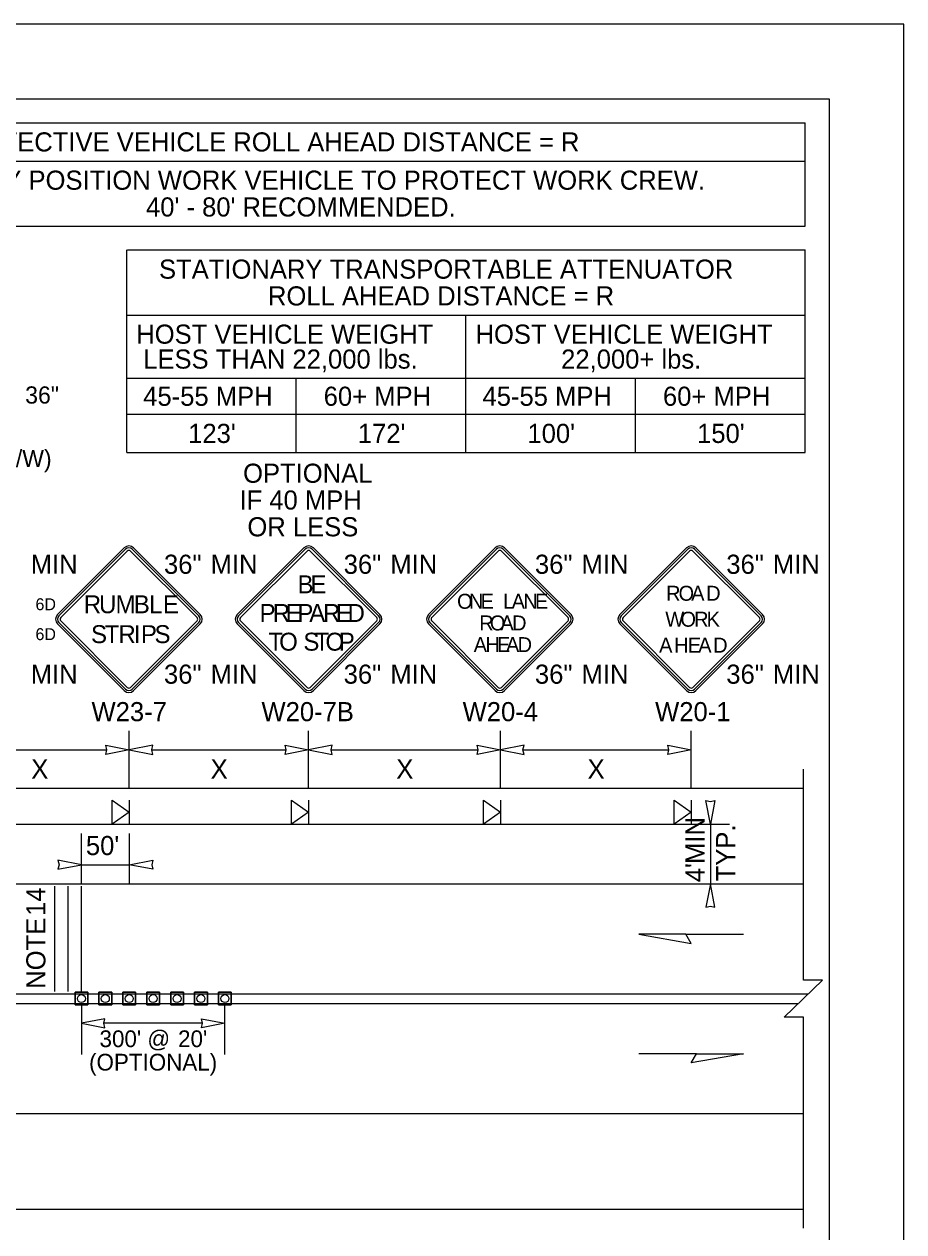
# Model space of a CAD drawing. Extents: x 99999.1 to 100095.7, y 99995 to 100010.7.
# Drawn here: x 100052.38 to 100056.06, y 100005.64 to 100010.69 of the extents above; entities that cross this region are included whole.
import ezdxf

# ---------------------------------------------------------------- set-up
doc = ezdxf.new("R2010")
doc.units = 0
for name, color, linetype in [('RD_ED_ShoulderPavedEdge', 7, 'Continuous'), ('RD_MK_LineDblYellowCenter', 7, 'Continuous'), ('RD_MK_LineEdgeWhite', 7, 'Continuous'), ('SH_GI_PlotLimits', 7, 'Continuous'), ('SH_GI_SheetBorder', 7, 'Continuous'), ('SH_TI_Tables', 7, 'Continuous'), ('TR_SN_ConstructionSigns', 7, 'Continuous'), ('TR_WZ_PortableSignMountBlk-Org', 7, 'Continuous'), ('TR_WZ_TrafficCone', 7, 'Continuous'), ('TR_WZ_WorkZoneDetails', 7, 'Continuous'), ('TR_WZ_WorkZoneTextCurrent', 7, 'Continuous')]:
    doc.layers.add(name, color=color, linetype=linetype)

msp = doc.modelspace()

# ---------------------------------------------------------------- linework, layer by layer
at = {"layer": 'RD_ED_ShoulderPavedEdge'}
for p, q in [((100040.1076, 100007.4923), (100055.6424, 100007.4923)), ((100040.1076, 100005.7323), (100055.6424, 100005.7323))]:
    msp.add_line(p, q, dxfattribs=at)
at = {"layer": 'RD_MK_LineDblYellowCenter'}
for p, q in [((100052.2733, 100006.6323), (100055.6631, 100006.6323)), ((100052.2733, 100006.5923), (100055.6218, 100006.5923))]:
    msp.add_line(p, q, dxfattribs=at)
at = {"layer": 'RD_MK_LineEdgeWhite'}
for p, q in [((100040.1076, 100007.0923), (100055.6424, 100007.0923)), ((100040.1076, 100006.1323), (100055.6424, 100006.1323))]:
    msp.add_line(p, q, dxfattribs=at)
at = {"layer": 'SH_GI_PlotLimits'}
msp.add_lwpolyline([(100039.0625, 99999.6875), (100056.0625, 99999.6875), (100056.0625, 100010.6875), (100039.0625, 100010.6875)], close=True, dxfattribs=at)
at = {"layer": 'SH_GI_SheetBorder'}
for p, q in [((100040, 100010.375), (100055.75, 100010.375)), ((100055.75, 100010.375), (100055.75, 100000))]:
    msp.add_line(p, q, dxfattribs=at)
at = {"layer": 'SH_TI_Tables'}
for p, q in [((100051.4347, 100010.275), (100055.65, 100010.275)), ((100055.65, 100009.843), (100055.65, 100010.275)), ((100051.4347, 100010.115), (100055.65, 100010.115)), ((100051.4347, 100009.843), (100055.65, 100009.843)), ((100052.8126, 100008.896), (100052.8126, 100009.743)), ((100052.8156, 100009.743), (100055.65, 100009.743)), ((100055.65, 100008.896), (100055.65, 100009.743)), ((100052.8126, 100009.471), (100055.65, 100009.471)), ((100054.2313, 100008.896), (100054.2313, 100009.471)), ((100052.8126, 100009.2069), (100054.2313, 100009.2069)), ((100053.5219, 100008.896), (100053.5219, 100009.2069)), ((100054.2313, 100009.2069), (100055.65, 100009.2069)), ((100054.9406, 100008.896), (100054.9406, 100009.2069)), ((100052.8126, 100009.056), (100054.2313, 100009.056)), ((100054.2313, 100009.056), (100055.65, 100009.056)), ((100052.8126, 100008.896), (100055.65, 100008.896))]:
    msp.add_line(p, q, dxfattribs=at)
at = {"layer": 'TR_SN_ConstructionSigns'}
for p, q in [((100052.8019, 100008.4972), (100052.5235, 100008.2188)), ((100052.8075, 100008.4917), (100052.529, 100008.2132)), ((100052.5368, 100008.2055), (100052.8152, 100008.4839)), ((100052.8285, 100008.4839), (100053.1069, 100008.2055)), ((100053.1146, 100008.2132), (100052.8362, 100008.4917)), ((100053.1201, 100008.2188), (100052.8417, 100008.4972)), ((100053.5535, 100008.4972), (100053.275, 100008.2188)), ((100053.559, 100008.4917), (100053.2806, 100008.2132)), ((100053.2883, 100008.2055), (100053.5667, 100008.4839)), ((100053.58, 100008.4839), (100053.8584, 100008.2055)), ((100053.8661, 100008.2132), (100053.5877, 100008.4917)), ((100053.8717, 100008.2188), (100053.5932, 100008.4972)), ((100054.3532, 100008.4972), (100054.0747, 100008.2188)), ((100054.3587, 100008.4917), (100054.0803, 100008.2132)), ((100054.088, 100008.2055), (100054.3664, 100008.4839)), ((100054.3797, 100008.4839), (100054.6581, 100008.2055)), ((100054.6658, 100008.2132), (100054.3874, 100008.4917)), ((100054.6714, 100008.2188), (100054.3929, 100008.4972)), ((100055.1535, 100008.4972), (100054.875, 100008.2188)), ((100055.159, 100008.4917), (100054.8806, 100008.2132)), ((100054.8883, 100008.2055), (100055.1667, 100008.4839)), ((100055.18, 100008.4839), (100055.4584, 100008.2055)), ((100055.4661, 100008.2132), (100055.1877, 100008.4917)), ((100055.4717, 100008.2188), (100055.1932, 100008.4972)), ((100052.5235, 100008.179), (100052.8019, 100007.9006)), ((100052.529, 100008.1845), (100052.8075, 100007.9061)), ((100052.8152, 100007.9138), (100052.5368, 100008.1923)), ((100053.1069, 100008.1923), (100052.8285, 100007.9138)), ((100052.8362, 100007.9061), (100053.1146, 100008.1845)), ((100052.8417, 100007.9006), (100053.1201, 100008.179)), ((100053.275, 100008.179), (100053.5535, 100007.9006)), ((100053.2806, 100008.1845), (100053.559, 100007.9061)), ((100053.5667, 100007.9138), (100053.2883, 100008.1923)), ((100053.8584, 100008.1923), (100053.58, 100007.9138)), ((100053.5877, 100007.9061), (100053.8661, 100008.1845)), ((100053.5932, 100007.9006), (100053.8717, 100008.179)), ((100054.0747, 100008.179), (100054.3532, 100007.9006)), ((100054.0803, 100008.1845), (100054.3587, 100007.9061)), ((100054.3664, 100007.9138), (100054.088, 100008.1923)), ((100054.6581, 100008.1923), (100054.3797, 100007.9138)), ((100054.3874, 100007.9061), (100054.6658, 100008.1845)), ((100054.3929, 100007.9006), (100054.6714, 100008.179)), ((100054.875, 100008.179), (100055.1535, 100007.9006)), ((100054.8806, 100008.1845), (100055.159, 100007.9061)), ((100055.1667, 100007.9138), (100054.8883, 100008.1923)), ((100055.4584, 100008.1923), (100055.18, 100007.9138)), ((100055.1877, 100007.9061), (100055.4661, 100008.1845)), ((100055.1932, 100007.9006), (100055.4717, 100008.179))]:
    msp.add_line(p, q, dxfattribs=at)
for centre, radius, start, end in [((100052.8218, 100008.4773), 0.0281, 45, 135), ((100052.8218, 100008.4773), 0.0203, 45, 135), ((100052.8218, 100008.4773), 0.00937, 45, 135), ((100053.5733, 100008.4773), 0.0281, 45, 135), ((100053.5733, 100008.4773), 0.0203, 45, 135), ((100053.5733, 100008.4773), 0.00937, 45, 135), ((100054.373, 100008.4773), 0.0281, 45, 135), ((100054.373, 100008.4773), 0.0203, 45, 135), ((100054.373, 100008.4773), 0.00937, 45, 135), ((100055.1733, 100008.4773), 0.0281, 45, 135), ((100055.1733, 100008.4773), 0.0203, 45, 135), ((100055.1733, 100008.4773), 0.00937, 45, 135), ((100052.5434, 100008.1989), 0.0281, 135, 225), ((100052.5434, 100008.1989), 0.0203, 135, 225), ((100052.5434, 100008.1989), 0.00937, 135, 225), ((100053.1003, 100008.1989), 0.00937, 315, 45), ((100053.1003, 100008.1989), 0.0203, 315, 45), ((100053.1003, 100008.1989), 0.0281, 315, 45), ((100053.2949, 100008.1989), 0.0281, 135, 225), ((100053.2949, 100008.1989), 0.0203, 135, 225), ((100053.2949, 100008.1989), 0.00937, 135, 225), ((100053.8518, 100008.1989), 0.00937, 315, 45), ((100053.8518, 100008.1989), 0.0203, 315, 45), ((100053.8518, 100008.1989), 0.0281, 315, 45), ((100054.0946, 100008.1989), 0.0281, 135, 225), ((100054.0946, 100008.1989), 0.0203, 135, 225), ((100054.0946, 100008.1989), 0.00937, 135, 225), ((100054.6515, 100008.1989), 0.00937, 315, 45), ((100054.6515, 100008.1989), 0.0203, 315, 45), ((100054.6515, 100008.1989), 0.0281, 315, 45), ((100054.8949, 100008.1989), 0.0281, 135, 225), ((100054.8949, 100008.1989), 0.0203, 135, 225), ((100054.8949, 100008.1989), 0.00937, 135, 225), ((100055.4518, 100008.1989), 0.00937, 315, 45), ((100055.4518, 100008.1989), 0.0203, 315, 45), ((100055.4518, 100008.1989), 0.0281, 315, 45), ((100052.8218, 100007.9205), 0.0281, 225, 315), ((100052.8218, 100007.9205), 0.0203, 225, 315), ((100052.8218, 100007.9205), 0.00937, 225, 315), ((100053.5733, 100007.9205), 0.0281, 225, 315), ((100053.5733, 100007.9205), 0.0203, 225, 315), ((100053.5733, 100007.9205), 0.00937, 225, 315), ((100054.373, 100007.9205), 0.0281, 225, 315), ((100054.373, 100007.9205), 0.0203, 225, 315), ((100054.373, 100007.9205), 0.00937, 225, 315), ((100055.1733, 100007.9205), 0.0281, 225, 315), ((100055.1733, 100007.9205), 0.0203, 225, 315), ((100055.1733, 100007.9205), 0.00937, 225, 315)]:
    msp.add_arc(centre, radius, start, end, dxfattribs=at)
at = {"layer": 'TR_WZ_PortableSignMountBlk-Org'}
for p, q in [((100052.8233, 100007.4422), (100052.8233, 100007.3422)), ((100053.5733, 100007.4422), (100053.5733, 100007.3422)), ((100054.3761, 100007.4422), (100054.3761, 100007.3422)), ((100055.1733, 100007.4422), (100055.1733, 100007.3422))]:
    msp.add_line(p, q, dxfattribs=at)
for points in [[(100052.8233, 100007.3923), (100052.7515, 100007.3422), (100052.7515, 100007.4422)], [(100053.5733, 100007.3923), (100053.5015, 100007.3422), (100053.5015, 100007.4422)], [(100054.3761, 100007.3923), (100054.3042, 100007.3422), (100054.3042, 100007.4422)], [(100055.1733, 100007.3923), (100055.1015, 100007.3422), (100055.1015, 100007.4422)]]:
    msp.add_lwpolyline(points, close=True, dxfattribs=at)
at = {"layer": 'TR_WZ_TrafficCone'}
for points in [[(100052.65, 100006.5857), (100052.5967, 100006.5857), (100052.5967, 100006.639), (100052.65, 100006.639), (100052.65, 100006.5857)], [(100052.65, 100006.639), (100052.5967, 100006.639), (100052.5967, 100006.5857), (100052.65, 100006.5857), (100052.65, 100006.639)], [(100052.75, 100006.5857), (100052.6967, 100006.5857), (100052.6967, 100006.639), (100052.75, 100006.639), (100052.75, 100006.5857)], [(100052.75, 100006.639), (100052.6967, 100006.639), (100052.6967, 100006.5857), (100052.75, 100006.5857), (100052.75, 100006.639)], [(100052.85, 100006.5857), (100052.7967, 100006.5857), (100052.7967, 100006.639), (100052.85, 100006.639), (100052.85, 100006.5857)], [(100052.85, 100006.639), (100052.7967, 100006.639), (100052.7967, 100006.5857), (100052.85, 100006.5857), (100052.85, 100006.639)], [(100052.95, 100006.5857), (100052.8967, 100006.5857), (100052.8967, 100006.639), (100052.95, 100006.639), (100052.95, 100006.5857)], [(100052.95, 100006.639), (100052.8967, 100006.639), (100052.8967, 100006.5857), (100052.95, 100006.5857), (100052.95, 100006.639)], [(100053.05, 100006.5857), (100052.9967, 100006.5857), (100052.9967, 100006.639), (100053.05, 100006.639), (100053.05, 100006.5857)], [(100053.05, 100006.639), (100052.9967, 100006.639), (100052.9967, 100006.5857), (100053.05, 100006.5857), (100053.05, 100006.639)], [(100053.15, 100006.5857), (100053.0967, 100006.5857), (100053.0967, 100006.639), (100053.15, 100006.639), (100053.15, 100006.5857)], [(100053.15, 100006.639), (100053.0967, 100006.639), (100053.0967, 100006.5857), (100053.15, 100006.5857), (100053.15, 100006.639)], [(100053.25, 100006.5857), (100053.1967, 100006.5857), (100053.1967, 100006.639), (100053.25, 100006.639), (100053.25, 100006.5857)], [(100053.25, 100006.639), (100053.1967, 100006.639), (100053.1967, 100006.5857), (100053.25, 100006.5857), (100053.25, 100006.639)]]:
    msp.add_lwpolyline(points, dxfattribs=at)
for centre in [(100052.6233, 100006.6123), (100052.7233, 100006.6123), (100052.8233, 100006.6123), (100052.9233, 100006.6123), (100053.0233, 100006.6123), (100053.1233, 100006.6123), (100053.2233, 100006.6123)]:
    msp.add_circle(centre, 0.0167, dxfattribs=at)
at = {"layer": 'TR_WZ_WorkZoneDetails'}
for p, q in [((100052.8233, 100007.4923), (100052.8233, 100007.7323)), ((100053.5733, 100007.4923), (100053.5733, 100007.7323)), ((100054.3761, 100007.4923), (100054.3761, 100007.7323)), ((100055.1733, 100007.4921), (100055.1733, 100007.7323)), ((100052.1671, 100007.6523), (100052.7296, 100007.6523)), ((100052.9171, 100007.6523), (100053.4796, 100007.6523)), ((100053.6671, 100007.6523), (100054.2823, 100007.6523)), ((100054.4698, 100007.6523), (100055.0796, 100007.6523)), ((100052.0733, 100007.3422), (100055.1733, 100007.3422)), ((100055.1733, 100007.3422), (100055.3333, 100007.3422)), ((100055.2533, 100007.3422), (100055.2533, 100007.0923)), ((100052.6233, 100007.0923), (100052.6233, 100007.3023)), ((100052.8233, 100007.3023), (100052.8233, 100007.0923)), ((100052.6233, 100007.1723), (100052.8233, 100007.1723)), ((100052.5128, 100006.6423), (100052.5128, 100007.0823)), ((100052.5685, 100006.6423), (100052.5685, 100007.0823)), ((100052.6233, 100006.6423), (100052.6233, 100007.0823)), ((100055.1733, 100007.0923), (100055.3333, 100007.0923)), ((100055.1513, 100006.8816), (100055.3924, 100006.8816)), ((100052.6233, 100006.589), (100052.6233, 100006.379)), ((100053.2233, 100006.379), (100053.2233, 100006.589)), ((100053.1296, 100006.509), (100052.7171, 100006.509)), ((100055.1959, 100006.3816), (100054.9548, 100006.3816))]:
    msp.add_line(p, q, dxfattribs=at)
for points in [[(100052.8233, 100007.6523), (100052.7251, 100007.6331), (100052.7296, 100007.6523), (100052.7251, 100007.6716)], [(100052.8233, 100007.6523), (100052.9216, 100007.6331), (100052.9171, 100007.6523), (100052.9216, 100007.6716)], [(100053.5733, 100007.6523), (100053.4751, 100007.6331), (100053.4796, 100007.6523), (100053.4751, 100007.6716)], [(100053.5733, 100007.6523), (100053.6716, 100007.6331), (100053.6671, 100007.6523), (100053.6716, 100007.6716)], [(100054.3761, 100007.6523), (100054.2778, 100007.6331), (100054.2823, 100007.6523), (100054.2778, 100007.6716)], [(100054.3761, 100007.6523), (100054.4743, 100007.6331), (100054.4698, 100007.6523), (100054.4743, 100007.6716)], [(100055.1733, 100007.6523), (100055.0751, 100007.6331), (100055.0796, 100007.6523), (100055.0751, 100007.6716)], [(100055.2533, 100007.3422), (100055.2341, 100007.4405), (100055.2533, 100007.436), (100055.2726, 100007.4405)], [(100052.6233, 100007.1723), (100052.5251, 100007.1916), (100052.5296, 100007.1723), (100052.5251, 100007.1531)], [(100052.8233, 100007.1723), (100052.9216, 100007.1916), (100052.9171, 100007.1723), (100052.9216, 100007.1531)], [(100055.2533, 100007.0923), (100055.2341, 100006.9941), (100055.2533, 100006.9986), (100055.2726, 100006.9941)], [(100054.9548, 100006.8816), (100055.1736, 100006.843), (100055.1513, 100006.8816)], [(100052.6233, 100006.509), (100052.7216, 100006.4897), (100052.7171, 100006.509), (100052.7216, 100006.5283)], [(100053.2233, 100006.509), (100053.1251, 100006.4897), (100053.1296, 100006.509), (100053.1251, 100006.5283)], [(100055.3924, 100006.3816), (100055.1736, 100006.343), (100055.1959, 100006.3816)]]:
    msp.add_lwpolyline(points, close=True, dxfattribs=at)
msp.add_lwpolyline([(100055.6424, 100005.6523), (100055.6424, 100006.5349), (100055.5624, 100006.5349), (100055.7225, 100006.6898), (100055.6424, 100006.6898), (100055.6424, 100007.5723)], dxfattribs=at)

# ---------------------------------------------------------------- texts
at = {"layer": 'SH_TI_Tables'}
for s, p in [('PROTECTIVE VEHICLE ROLL AHEAD DISTANCE = R', (100052.0577, 100010.155)), ('STRATEGICALLY POSITION WORK VEHICLE TO PROTECT WORK CREW.', (100051.4984, 100009.995)), ("40' - 80'", (100052.8935, 100009.883)), ('RECOMMENDED.', (100053.297, 100009.883)), ('STATIONARY TRANSPORTABLE ATTENUATOR', (100052.9479, 100009.623)), ('ROLL AHEAD DISTANCE = R', (100053.4035, 100009.511)), ('HOST VEHICLE WEIGHT', (100052.8526, 100009.351)), ('HOST VEHICLE WEIGHT', (100054.2713, 100009.351)), ('LESS THAN 22,000 lbs.', (100052.8817, 100009.2469)), ('22,000+ lbs.', (100054.6295, 100009.2469)), ('45-55 MPH', (100052.8818, 100009.0914)), ('60+ MPH', (100053.6365, 100009.0914)), ('45-55 MPH', (100054.3006, 100009.0914)), ('60+ MPH', (100055.0552, 100009.0914)), ("123'", (100053.0698, 100008.936)), ("172'", (100053.7792, 100008.936)), ("100'", (100054.4885, 100008.936)), ("150'", (100055.1979, 100008.936))]:
    msp.add_text(s, height=0.08, rotation=360, dxfattribs=at).set_placement(p)
at = {"layer": 'TR_SN_ConstructionSigns'}
for s, height, p in [('36"', 0.072, (100052.3882, 100009.1006)), ('R10-6L (B/W)', 0.072, (100051.9104, 100008.8351)), ('MIN', 0.08, (100052.4114, 100008.3887)), ('36"', 0.08, (100052.9686, 100008.3887)), ('MIN', 0.08, (100053.1636, 100008.3887)), ('36"', 0.08, (100053.7201, 100008.3887)), ('MIN', 0.08, (100053.9151, 100008.3887)), ('36"', 0.08, (100054.5198, 100008.3887)), ('MIN', 0.08, (100054.7148, 100008.3887)), ('36"', 0.08, (100055.3201, 100008.3887)), ('MIN', 0.08, (100055.5151, 100008.3887)), ('MIN', 0.08, (100052.4114, 100007.9291)), ('36"', 0.08, (100052.9686, 100007.9291)), ('MIN', 0.08, (100053.1636, 100007.9291)), ('36"', 0.08, (100053.7201, 100007.9291)), ('MIN', 0.08, (100053.9151, 100007.9291)), ('36"', 0.08, (100054.5198, 100007.9291)), ('MIN', 0.08, (100054.7148, 100007.9291)), ('36"', 0.08, (100055.3201, 100007.9291)), ('MIN', 0.08, (100055.5151, 100007.9291)), ('W23-7', 0.08, (100052.6656, 100007.7723)), ('W20-7B', 0.08, (100053.3763, 100007.7723)), ('W20-4', 0.08, (100054.2176, 100007.7723)), ('W20-1', 0.08, (100055.0224, 100007.7723))]:
    msp.add_text(s, height=height, rotation=360, dxfattribs=at).set_placement(p)
for s, height, p in [('OPTIONAL', 0.08, (100053.2994, 100008.7694)), ('IF 40 MPH', 0.08, (100053.2843, 100008.6574)), ('OR LESS', 0.08, (100053.3175, 100008.5454)), ('B', 0.075, (100053.5271, 100008.3074)), ('E', 0.075, (100053.5814, 100008.3074)), ('R', 0.0625, (100055.0683, 100008.2762)), ('O', 0.0625, (100055.1204, 100008.2762)), ('A', 0.0625, (100055.1732, 100008.2762)), ('D', 0.0625, (100055.2359, 100008.2762)), ('6D', 0.05, (100052.4313, 100008.2364)), ('R', 0.075, (100052.6332, 100008.2239)), ('U', 0.075, (100052.697, 100008.2239)), ('M', 0.075, (100052.766, 100008.2239)), ('B', 0.075, (100052.8425, 100008.2239)), ('L', 0.075, (100052.9062, 100008.2239)), ('E', 0.075, (100052.964, 100008.2239)), ('O', 0.0625, (100054.1943, 100008.2426)), ('N', 0.0625, (100054.2437, 100008.2426)), ('E', 0.0625, (100054.2924, 100008.2426)), ('L', 0.0625, (100054.3868, 100008.2426)), ('A', 0.0625, (100054.4224, 100008.2426)), ('N', 0.0625, (100054.4712, 100008.2426)), ('E', 0.0625, (100054.5199, 100008.2426)), ('P', 0.075, (100053.3684, 100008.1874)), ('R', 0.075, (100053.4237, 100008.1874)), ('E', 0.075, (100053.4769, 100008.1874)), ('P', 0.075, (100053.5264, 100008.1874)), ('A', 0.075, (100053.5763, 100008.1874)), ('R', 0.075, (100053.6335, 100008.1874)), ('E', 0.075, (100053.6868, 100008.1874)), ('D', 0.075, (100053.7362, 100008.1874)), ('W', 0.0625, (100055.065, 100008.1676)), ('O', 0.0625, (100055.1282, 100008.1676)), ('R', 0.0625, (100055.1855, 100008.1676)), ('K', 0.0625, (100055.2379, 100008.1676)), ('S', 0.075, (100052.6636, 100008.0989)), ('S', 0.075, (100052.9291, 100008.0989)), ('R', 0.0625, (100054.2868, 100008.152)), ('O', 0.0625, (100054.3312, 100008.152)), ('A', 0.0625, (100054.3755, 100008.152)), ('D', 0.0625, (100054.4243, 100008.152)), ('6D', 0.05, (100052.4313, 100008.1114)), ('T', 0.075, (100052.7206, 100008.0989)), ('R', 0.075, (100052.7783, 100008.0989)), ('I', 0.075, (100052.8421, 100008.0989)), ('P', 0.075, (100052.8721, 100008.0989)), ('T', 0.075, (100053.4051, 100008.0674)), ('O', 0.075, (100053.4502, 100008.0674)), ('S', 0.075, (100053.5516, 100008.0674)), ('T', 0.075, (100053.5988, 100008.0674)), ('O', 0.075, (100053.6439, 100008.0674)), ('P', 0.075, (100053.6996, 100008.0674)), ('A', 0.0625, (100054.2637, 100008.0614)), ('H', 0.0625, (100054.3124, 100008.0614)), ('E', 0.0625, (100054.3612, 100008.0614)), ('A', 0.0625, (100054.3987, 100008.0614)), ('D', 0.0625, (100054.4474, 100008.0614)), ('A', 0.0625, (100055.039, 100008.0591)), ('H', 0.0625, (100055.1015, 100008.0591)), ('E', 0.0625, (100055.159, 100008.0591)), ('A', 0.0625, (100055.2027, 100008.0591)), ('D', 0.0625, (100055.2652, 100008.0591))]:
    msp.add_text(s, height=height, dxfattribs=at).set_placement(p)
at = {"layer": 'TR_WZ_WorkZoneDetails'}
for s, p in [('14', (100052.4728, 100006.9581)), ('NOTE', (100052.4728, 100006.6533))]:
    msp.add_text(s, height=0.08, rotation=90, dxfattribs=at).set_placement(p)
at = {"layer": 'TR_WZ_WorkZoneTextCurrent'}
for s, height, p in [('X', 0.08, (100052.4136, 100007.5323)), ('X', 0.08, (100053.1636, 100007.5323)), ('X', 0.08, (100053.94, 100007.5323)), ('X', 0.08, (100054.74, 100007.5323)), ("50'", 0.08, (100052.6421, 100007.2123)), ("300' @", 0.07, (100052.6991, 100006.4093)), ("20'", 0.07, (100053.0275, 100006.4093)), ('(OPTIONAL)', 0.07, (100052.6553, 100006.3113))]:
    msp.add_text(s, height=height, dxfattribs=at).set_placement(p)
for s, p in [('MIN', (100055.2293, 100007.1754)), ('TYP.', (100055.3573, 100007.1026)), ("4'", (100055.2293, 100007.0989))]:
    msp.add_text(s, height=0.08, rotation=90, dxfattribs=at).set_placement(p)

doc.saveas('drawing.dxf')
